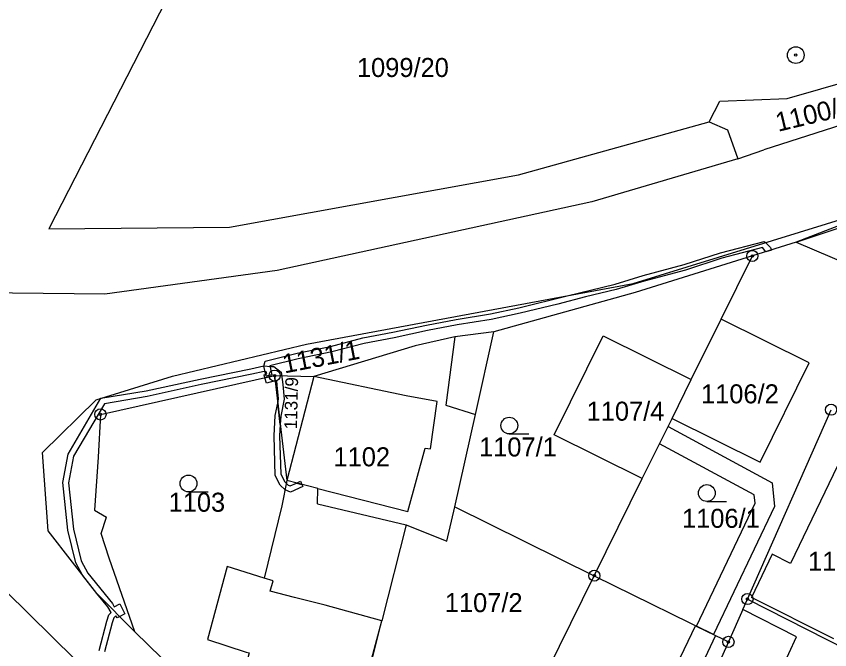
# Model space of a CAD drawing. Extents: x -621172 to -616925, y -1123899 to -1119548.
# Drawn here: x -619097.5 to -619024.8, y -1121597.8 to -1121541.1 of the extents above; entities that cross this region are included whole.
import ezdxf

# ---------------------------------------------------------------- set-up
doc = ezdxf.new("R2010")
doc.units = 0
for name, color, linetype in [('Vrstva 1', 7, 'Continuous'), ('Vrstva 18', 7, 'Continuous'), ('Vrstva 19', 7, 'Continuous'), ('Vrstva 24', 7, 'Continuous'), ('Vrstva 25', 7, 'Continuous'), ('Vrstva 4', 7, 'Continuous')]:
    doc.layers.add(name, color=color, linetype=linetype)

msp = doc.modelspace()

# ---------------------------------------------------------------- linework, layer by layer
at = {"layer": 'Vrstva 1'}
for points in [[(-619064.91, -1121502.3), (-619094.57, -1121560.13)], [(-619028.55, -1121548.46), (-619019.32, -1121545.81)], [(-619035.52, -1121550.57), (-619034.59, -1121548.71)], [(-619034.59, -1121548.71), (-619028.55, -1121548.46)], [(-619018.27, -1121549.11), (-619030.65, -1121553.07)], [(-619052.57, -1121555.29), (-619035.52, -1121550.57)], [(-619035.52, -1121550.57), (-619033.9, -1121551.28)], [(-619033.9, -1121551.28), (-619032.97, -1121553.86)], [(-619032.97, -1121553.86), (-619030.65, -1121553.07)], [(-619032.97, -1121553.86), (-619046.03, -1121557.71)], [(-619078.41, -1121559.99), (-619052.57, -1121555.29)], [(-619042.33, -1121565.01), (-619017.42, -1121557.32)], [(-619017.42, -1121557.32), (-619027.77, -1121561.33)], [(-619027.77, -1121561.33), (-619016.17, -1121557.43)], [(-619046.03, -1121557.71), (-619074.14, -1121563.86)], [(-619094.57, -1121560.13), (-619078.41, -1121559.99)], [(-619034.53, -1121562.26), (-619030.63, -1121561.25)], [(-619030.63, -1121561.25), (-619030.51, -1121561.36)], [(-619030.77, -1121561.81), (-619034.39, -1121562.74)], [(-619027.77, -1121561.33), (-619031.67, -1121562.55)], [(-619030.48, -1121562.18), (-619030.77, -1121561.81)], [(-619030.51, -1121561.36), (-619030.05, -1121561.8)], [(-619030.05, -1121561.8), (-619029.97, -1121562.02)], [(-619027.77, -1121561.33), (-619019.72, -1121564.75)], [(-619031.67, -1121562.55), (-619042.15, -1121565.81)], [(-619037.77, -1121563.33), (-619034.53, -1121562.26)], [(-619034.39, -1121562.74), (-619037.65, -1121563.82)], [(-619034.46, -1121568.2), (-619031.67, -1121562.55)], [(-619029.97, -1121562.02), (-619030.48, -1121562.18)], [(-619041.44, -1121564.31), (-619037.77, -1121563.33)], [(-619074.14, -1121563.86), (-619089.55, -1121565.96)], [(-619037.65, -1121563.82), (-619041.35, -1121564.8)], [(-619043.95, -1121565.07), (-619041.44, -1121564.31)], [(-619041.35, -1121564.8), (-619043.84, -1121565.55)], [(-619089.55, -1121565.96), (-619122.59, -1121565.6)], [(-619071.52, -1121570.45), (-619042.33, -1121565.01)], [(-619048.24, -1121566.11), (-619043.95, -1121565.07)], [(-619043.84, -1121565.55), (-619046.59, -1121566.22)], [(-619042.15, -1121565.81), (-619054.78, -1121569.35)], [(-619052.55, -1121567.18), (-619048.24, -1121566.11)], [(-619046.59, -1121566.22), (-619049.07, -1121566.87)], [(-619049.07, -1121566.87), (-619052.42, -1121567.67)], [(-619058.14, -1121568.23), (-619055.09, -1121567.73)], [(-619055.09, -1121567.73), (-619052.55, -1121567.18)], [(-619052.42, -1121567.67), (-619055.01, -1121568.23)], [(-619060.81, -1121568.73), (-619058.14, -1121568.23)], [(-619055.01, -1121568.23), (-619058.05, -1121568.72)], [(-619037.13, -1121573.59), (-619034.46, -1121568.2)], [(-619026.59, -1121572.11), (-619034.46, -1121568.2)], [(-619063.8, -1121569.37), (-619060.81, -1121568.73)], [(-619060.7, -1121569.22), (-619063.7, -1121569.86)], [(-619058.05, -1121568.72), (-619060.7, -1121569.22)], [(-619069.38, -1121570.64), (-619066.48, -1121569.88)], [(-619066.48, -1121569.88), (-619063.8, -1121569.37)], [(-619063.7, -1121569.86), (-619066.38, -1121570.37)], [(-619058.27, -1121569.78), (-619061.81, -1121570.59)], [(-619054.78, -1121569.35), (-619058.27, -1121569.78)], [(-619056.41, -1121576.73), (-619054.78, -1121569.35)], [(-619049.39, -1121578.55), (-619045.01, -1121569.7)], [(-619045.01, -1121569.7), (-619037.13, -1121573.59)], [(-619083.5, -1121573.29), (-619071.52, -1121570.45)], [(-619072.37, -1121571.25), (-619069.38, -1121570.64)], [(-619061.81, -1121570.59), (-619070.86, -1121573.33)], [(-619066.38, -1121570.37), (-619069.26, -1121571.13)], [(-619075.23, -1121571.97), (-619072.37, -1121571.25)], [(-619069.26, -1121571.13), (-619072.28, -1121571.74)], [(-619075.33, -1121572.41), (-619075.23, -1121571.97)], [(-619072.28, -1121571.74), (-619074.81, -1121572.37)], [(-619030.97, -1121580.98), (-619026.59, -1121572.11)], [(-619081.04, -1121573.56), (-619076.52, -1121572.65)], [(-619076.52, -1121572.65), (-619075.35, -1121572.38)], [(-619075.31, -1121572.88), (-619076.42, -1121573.13)], [(-619075.35, -1121572.38), (-619074.73, -1121572.44)], [(-619075.13, -1121573.3), (-619075.33, -1121572.41)], [(-619075.13, -1121572.9), (-619075.31, -1121572.88)], [(-619075.08, -1121573.1), (-619075.13, -1121572.9)], [(-619074.81, -1121572.37), (-619074.64, -1121573.19)], [(-619074.73, -1121572.44), (-619074.45, -1121572.44)], [(-619074.45, -1121572.44), (-619073.79, -1121572.93)], [(-619090.33, -1121575.41), (-619083.5, -1121573.29)], [(-619089.95, -1121576.72), (-619074.38, -1121573.25)], [(-619085.86, -1121574.61), (-619081.04, -1121573.56)], [(-619076.42, -1121573.13), (-619080.94, -1121574.04)], [(-619075.32, -1121573.17), (-619075.08, -1121573.1)], [(-619075.24, -1121573.44), (-619075.32, -1121573.17)], [(-619074.38, -1121573.25), (-619075.24, -1121573.44)], [(-619074.33, -1121573.72), (-619075.1, -1121573.94), (-619075.24, -1121573.44), (-619074.38, -1121573.25), (-619074.33, -1121573.72)], [(-619074.64, -1121573.19), (-619075.13, -1121573.3)], [(-619074.38, -1121573.25), (-619070.86, -1121573.33)], [(-619074.38, -1121573.25), (-619073.28, -1121582.64)], [(-619074.33, -1121573.72), (-619074.38, -1121573.25)], [(-619073.79, -1121572.93), (-619073.64, -1121574.04)], [(-619070.86, -1121573.33), (-619073.28, -1121582.64)], [(-619038.85, -1121577.08), (-619037.13, -1121573.59)], [(-619080.94, -1121574.04), (-619085.76, -1121575.11)], [(-619074.19, -1121573.68), (-619074.33, -1121573.72)], [(-619074.14, -1121574.1), (-619074.19, -1121573.68)], [(-619074.02, -1121575.33), (-619074.14, -1121574.1)], [(-619073.64, -1121574.04), (-619073.52, -1121575.35)], [(-619089.91, -1121575.28), (-619085.86, -1121574.61)], [(-619095.12, -1121580.12), (-619090.33, -1121575.41)], [(-619092.84, -1121580.28), (-619089.91, -1121575.28)], [(-619089.59, -1121575.77), (-619092.36, -1121580.46)], [(-619085.76, -1121575.11), (-619089.59, -1121575.77)], [(-619074.09, -1121575.7), (-619073.87, -1121577.63), (-619073.93, -1121578.63), (-619073.82, -1121582.06), (-619073.48, -1121582.76), (-619073.33, -1121582.9), (-619073.18, -1121583.04), (-619072.98, -1121583.12), (-619072.42, -1121582.86), (-619071.94, -1121582.98), (-619071.86, -1121583.15), (-619072.96, -1121583.66), (-619073.44, -1121583.46), (-619073.88, -1121583.06), (-619074.32, -1121582.18), (-619074.43, -1121578.63), (-619074.32, -1121576.82), (-619074.09, -1121575.7)], [(-619074.09, -1121575.7), (-619074.02, -1121575.33)], [(-619073.87, -1121577.63), (-619074.09, -1121575.7)], [(-619073.52, -1121575.35), (-619073.82, -1121576.88)], [(-619032.11, -1121593.23), (-619024.63, -1121576.3)], [(-619089.95, -1121576.72), (-619090.14, -1121580.53)], [(-619073.82, -1121576.88), (-619073.87, -1121577.63)], [(-619058.28, -1121584.98), (-619056.41, -1121576.73)], [(-619041.51, -1121582.46), (-619038.85, -1121577.08)], [(-619038.85, -1121577.08), (-619030.97, -1121580.98)], [(-619039.97, -1121579.34), (-619039.21, -1121577.81)], [(-619039.21, -1121577.81), (-619029.89, -1121582.83)], [(-619041.51, -1121582.46), (-619049.39, -1121578.55)], [(-619031.5, -1121583.9), (-619039.97, -1121579.34)], [(-619094.63, -1121587.13), (-619095.12, -1121580.12)], [(-619093.3, -1121582.82), (-619092.84, -1121580.28)], [(-619092.36, -1121580.46), (-619092.8, -1121582.84)], [(-619090.14, -1121580.53), (-619090.48, -1121585.28)], [(-619092.86, -1121587.07), (-619093.3, -1121582.82)], [(-619092.8, -1121582.84), (-619092.36, -1121586.99)], [(-619073.28, -1121582.64), (-619073.73, -1121584.9)], [(-619070.53, -1121583.34), (-619073.28, -1121582.64)], [(-619072.42, -1121582.86), (-619072.07, -1121582.7), (-619071.94, -1121582.98), (-619072.42, -1121582.86)], [(-619045.8, -1121591.14), (-619041.51, -1121582.46)], [(-619029.89, -1121582.83), (-619029.69, -1121584.96)], [(-619070.56, -1121584.72), (-619070.53, -1121583.34)], [(-619031.43, -1121584.65), (-619031.5, -1121583.9)], [(-619090.48, -1121585.28), (-619089.4, -1121585.9)], [(-619073.73, -1121584.9), (-619075.3, -1121591.35)], [(-619070.56, -1121584.72), (-619062.61, -1121586.58)], [(-619058.97, -1121588.04), (-619058.28, -1121584.98)], [(-619058.28, -1121584.98), (-619045.8, -1121591.14)], [(-619036.68, -1121595.65), (-619031.43, -1121584.65)], [(-619029.69, -1121584.96), (-619035.15, -1121596.4)], [(-619089.89, -1121587.38), (-619089.4, -1121585.9)], [(-619062.61, -1121586.58), (-619064.81, -1121595.19)], [(-619062.61, -1121586.58), (-619058.97, -1121588.04)], [(-619090.27, -1121592.74), (-619094.63, -1121587.13)], [(-619092.14, -1121589.98), (-619092.86, -1121587.07)], [(-619092.36, -1121586.99), (-619091.66, -1121589.8)], [(-619089.16, -1121589.58), (-619089.89, -1121587.38)], [(-619086.87, -1121596.15), (-619089.16, -1121589.58)], [(-619091.55, -1121591.09), (-619092.14, -1121589.98)], [(-619091.66, -1121589.8), (-619091.08, -1121590.91)], [(-619078.62, -1121590.32), (-619080.37, -1121596.84)], [(-619075.3, -1121591.35), (-619078.62, -1121590.32)], [(-619090.27, -1121592.74), (-619091.55, -1121591.09)], [(-619091.08, -1121590.91), (-619088.87, -1121593.64)], [(-619051, -1121601.66), (-619045.8, -1121591.14)], [(-619045.8, -1121591.14), (-619033.81, -1121597.06)], [(-619090.17, -1121600.63), (-619098.37, -1121592.54)], [(-619086.87, -1121596.15), (-619090.27, -1121592.74)], [(-619089.29, -1121593.92), (-619090.27, -1121592.74)], [(-619032.52, -1121594.15), (-619032.11, -1121593.23)], [(-619032.11, -1121593.23), (-619023.25, -1121597.75)], [(-619089, -1121594.44), (-619089.29, -1121593.92)], [(-619088.87, -1121593.64), (-619088.72, -1121593.92)], [(-619088.72, -1121593.92), (-619088.22, -1121593.66)], [(-619088.22, -1121593.66), (-619087.76, -1121594.55)], [(-619089.37, -1121595.21), (-619089.19, -1121594.65)], [(-619089.19, -1121594.65), (-619089, -1121594.44)], [(-619088.58, -1121594.72), (-619088.75, -1121594.91)], [(-619088.47, -1121594.92), (-619088.58, -1121594.72)], [(-619087.76, -1121594.55), (-619088.22, -1121594.79), (-619088.47, -1121594.92)], [(-619032.52, -1121594.15), (-619033.81, -1121597.06)], [(-619027.72, -1121596.6), (-619032.52, -1121594.15)], [(-619090.07, -1121597.82), (-619089.37, -1121595.21)], [(-619088.89, -1121595.35), (-619089.59, -1121597.96)], [(-619088.75, -1121594.91), (-619088.89, -1121595.35)], [(-619067.13, -1121604.45), (-619064.81, -1121595.19)], [(-619078.56, -1121604.27), (-619086.87, -1121596.15)], [(-619049.24, -1121619.62), (-619048.51, -1121618.65), (-619047.54, -1121617.13), (-619046.73, -1121616.62), (-619038.42, -1121599.11), (-619036.75, -1121595.61), (-619034.96, -1121596.49), (-619036.62, -1121599.97), (-619044.98, -1121617.6), (-619045.13, -1121618.65), (-619046.08, -1121620.27), (-619046.63, -1121621.03), (-619049.24, -1121619.62)], [(-619046.63, -1121621.03), (-619049.24, -1121619.62), (-619048.51, -1121618.65), (-619047.54, -1121617.13), (-619046.73, -1121616.62), (-619038.42, -1121599.11), (-619036.75, -1121595.61), (-619034.96, -1121596.49), (-619036.62, -1121599.97), (-619044.98, -1121617.6), (-619045.13, -1121618.65), (-619046.08, -1121620.27), (-619046.63, -1121621.03)], [(-619035.15, -1121596.4), (-619036.68, -1121595.65)], [(-619080.37, -1121596.84), (-619076.91, -1121597.97)], [(-619029.78, -1121601.08), (-619027.72, -1121596.6)], [(-619033.81, -1121597.06), (-619034.93, -1121599.58)]]:
    msp.add_lwpolyline(points, dxfattribs=at)
at = {"layer": 'Vrstva 24'}
for centre, radius in [((-619027.79, -1121544.59), 0.75), ((-619027.79, -1121544.59), 0.1), ((-619031.67, -1121562.55), 0.5), ((-619031.67, -1121562.55), 0.1), ((-619074.38, -1121573.25), 0.5), ((-619074.38, -1121573.25), 0.1), ((-619024.63, -1121576.3), 0.5), ((-619089.95, -1121576.72), 0.5), ((-619089.95, -1121576.72), 0.1), ((-619045.8, -1121591.14), 0.5), ((-619045.8, -1121591.14), 0.1), ((-619032.11, -1121593.23), 0.5), ((-619032.11, -1121593.23), 0.1), ((-619033.81, -1121597.06), 0.5), ((-619033.81, -1121597.06), 0.1)]:
    msp.add_circle(centre, radius, dxfattribs=at)
at = {"layer": 'Vrstva 25'}
for p, q in [((-619053.4, -1121578.47), (-619051.65, -1121578.47)), ((-619082.08, -1121583.65), (-619080.33, -1121583.65)), ((-619035.74, -1121584.5), (-619033.99, -1121584.5))]:
    msp.add_line(p, q, dxfattribs=at)
for centre in [(-619053.4, -1121577.72), (-619082.08, -1121582.9), (-619035.74, -1121583.75)]:
    msp.add_circle(centre, 0.75, dxfattribs=at)
at = {"layer": 'Vrstva 4'}
for points in [[(-619058.27, -1121569.78), (-619059.07, -1121575.89)], [(-619062.63, -1121575.05), (-619070.86, -1121573.33)], [(-619059.84, -1121575.57), (-619062.63, -1121575.05)], [(-619060.44, -1121579.81), (-619059.84, -1121575.57)], [(-619059.07, -1121575.89), (-619056.41, -1121576.73)], [(-619062.46, -1121585.39), (-619060.91, -1121579.74)], [(-619060.91, -1121579.74), (-619060.44, -1121579.81)], [(-619024.07, -1121581.33), (-619028.26, -1121590.04)], [(-619070.53, -1121583.34), (-619062.46, -1121585.39)], [(-619029.89, -1121589.22), (-619031.76, -1121593.08)], [(-619028.26, -1121590.04), (-619029.89, -1121589.22)], [(-619072.59, -1121593.1), (-619074.79, -1121592.51), (-619074.51, -1121591.6), (-619075.3, -1121591.35)], [(-619069.86, -1121593.77), (-619072.59, -1121593.1)], [(-619024.38, -1121596.79), (-619031.76, -1121593.08)], [(-619064.81, -1121595.19), (-619069.86, -1121593.77)], [(-619076.91, -1121597.97), (-619076.66, -1121598.05), (-619077.69, -1121601.96), (-619067.34, -1121604.66), (-619064.81, -1121595.19)]]:
    msp.add_lwpolyline(points, dxfattribs=at)

# ---------------------------------------------------------------- texts
at = {"layer": 'Vrstva 18'}
for s, p in [('1099/20', (-619067.021, -1121546.55)), ('1107/1', (-619056.104, -1121580.48)), ('1103', (-619083.859, -1121585.42)), ('1106/1', (-619037.96, -1121586.86)), ('1107/2', (-619059.166, -1121594.4))]:
    msp.add_text(s, height=1.7, dxfattribs=at).set_placement(p)
for s, height, rotation, p in [('1100/2', 1.7, 13.5, (-619029.37, -1121551.458)), ('1131/1', 1.7, 11.12409, (-619073.495, -1121573.064)), ('1131/9', 1.14, 88.63965, (-619072.384, -1121578.061))]:
    msp.add_text(s, height=height, rotation=rotation, dxfattribs=at).set_placement(p)
at = {"layer": 'Vrstva 19'}
for s, p in [('1106/2', (-619036.262, -1121575.73)), ('1107/4', (-619046.491, -1121577.28)), ('1102', (-619069.117, -1121581.36)), ('1116/6', (-619026.696, -1121590.7))]:
    msp.add_text(s, height=1.7, dxfattribs=at).set_placement(p)

doc.saveas('drawing.dxf')
